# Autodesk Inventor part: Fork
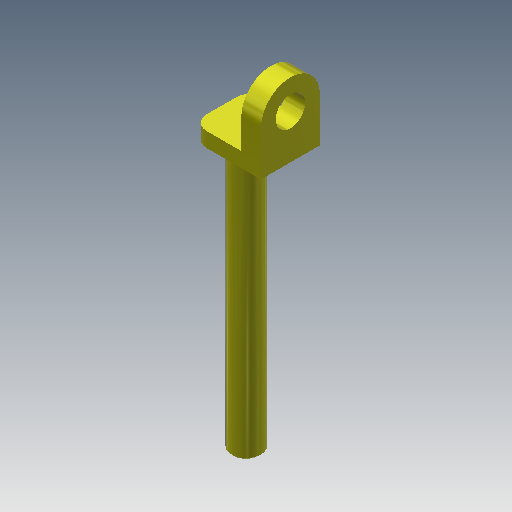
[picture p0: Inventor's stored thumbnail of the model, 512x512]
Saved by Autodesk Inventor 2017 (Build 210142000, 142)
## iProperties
Created: 2015-03
Part Number: Fork
Document SubType Name: Modeling
Designer: Administrator
Density: 1 g/cm^3
Mass: 2.44637 g
Surface Area: 18.5877 cm^2
Volume: 2.44637 cm^3
Material: Generic
Appearance: Smooth - Yellow
Author: Administrator
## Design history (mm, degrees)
sketch "Sketch1"
  geometry: L1 (0, 0)-(0, 3); L2 (0, 0)-(5, 0); L3 (5, 0)-(5, 6); L4 (5, 6)-(9, 6); L5 (9, 6)-(9, -9); L6 (9, -9)-(0, -9); L7 (5, 0)-(5, -6); L8 (5, -6)-(0, -6); L9 (0, -6)-(0, -9); L10 (0, 0)-(-5, 0); L11 (-5, -9)-(0, -9); L12 (-5, -6)-(0, -6); L13 (-5, -6)-(-5, -9)
  constraints: 26 end point, 5 perpendicular, 4 parallel, 2 symmetric about line, 1 vertical, 2 other
  dimensions: "d13" = 5 distance of L2.start L2.end; "d14" = 0 distance of L1.start L2.start; "d15" = 4 distance of L3.end L4.end; "d16" = 6 distance between parallel lines of L4 L2; "d17" = 3 distance of L8.end L6.end; "d18" = 6 distance between parallel lines of L2 L8; "d19" = 0 distance between parallel lines of L1 L9
extrude "Extrusion2" new body sketch "Sketch1" stored distance "d20" = 12; taper "d21" = 0 deg
fillet "Fillet1" dims "d22" = 6
sketch "Sketch3"
  geometry: L1 (18, 0)-(4, 0) reference; L2 (4, -12)-(18, -12) reference; L3 (11, 0)-(11, -12); C1 r 3 at (11, -6); 2 further points
  constraints: 3 midpoint, 2 end point, 1 centre point
  dimensions: "d23" = 6 diameter of C1
extrude "Extrusion3" join sketch "Sketch3" distance "d24" = 55; taper "d25" = 0 deg
sketch "Sketch4"
  geometry: C1 r 3 at (6, 9); A1 r 6 centre (6, 9) between (12, 9) and (0, 9) reference
  constraints: 1 centre point, 1 coincident
  dimensions: "d26" = 6 diameter of C1
extrude "Extrusion4" cut sketch "Sketch4" distance "d27" = 10; taper "d28" = 0 deg
chamfer "Chamfer1" distance "d29" = 0.5; stored, may be unused: second distance "d30" = 2, angle "d31" = 45 deg
fillet "Fillet2" dims "d32" = 3
body "Solid1"
